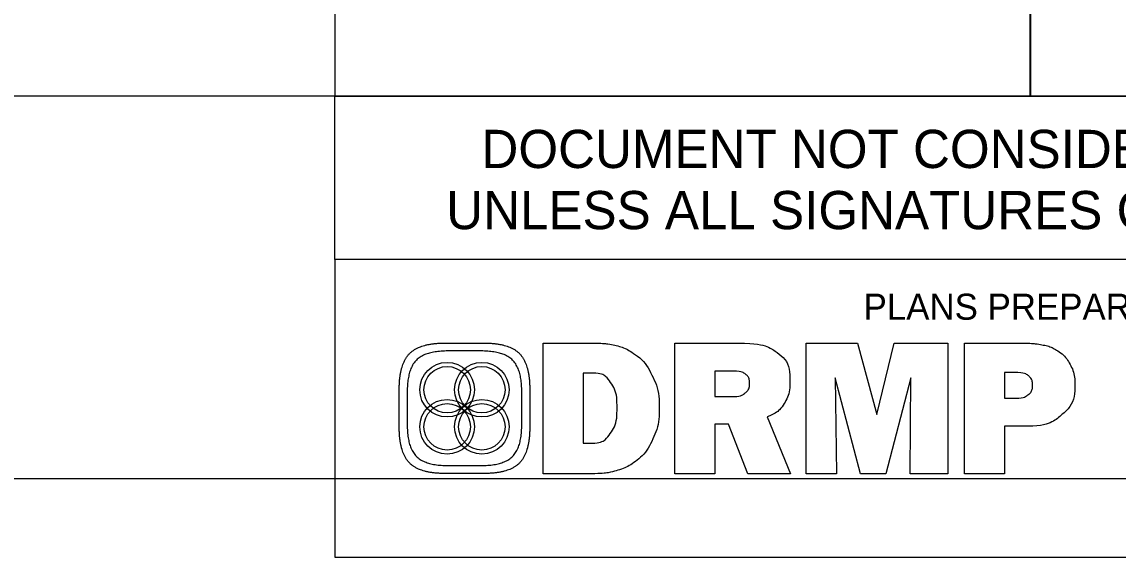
# Model space of a CAD drawing. Extents: x 573076.3 to 573113.7, y -55253.8 to -55199.3.
# Drawn here: x 573106.612 to 573109.767, y -55203.877 to -55202.337 of the extents above; entities that cross this region are included whole.
import ezdxf

# ---------------------------------------------------------------- set-up
doc = ezdxf.new("R2010")
doc.units = 0
for name, color, linetype in [('Pattern 1', 7, 'Continuous'), ('Pattern 2', 7, 'Continuous'), ('Pattern 3', 7, 'Continuous'), ('Scratch_Level_1', 7, 'Continuous'), ('Sheet Plan CELL', 7, 'Continuous'), ('Sheet Sticker Exception Certification CELL', 7, 'Continuous')]:
    doc.layers.add(name, color=color, linetype=linetype)

msp = doc.modelspace()

# ---------------------------------------------------------------- linework, layer by layer
at = {"layer": 'Pattern 1'}
for p, q in [((573107.8314, -55203.2607), (573107.9403, -55203.2607)), ((573108.8689, -55203.6369), (573108.8689, -55203.261)), ((573108.8689, -55203.261), (573109.0168, -55203.261)), ((573109.0168, -55203.261), (573109.073, -55203.4663)), ((573109.073, -55203.4663), (573109.1227, -55203.261)), ((573109.1227, -55203.261), (573109.2771, -55203.261)), ((573109.2771, -55203.261), (573109.2771, -55203.6369)), ((573107.9336, -55203.2836), (573107.8381, -55203.2836)), ((573109.026, -55203.6369), (573108.9528, -55203.3613)), ((573108.9528, -55203.3613), (573108.9568, -55203.6369)), ((573109.1705, -55203.3613), (573109.0989, -55203.6369)), ((573109.1687, -55203.6369), (573109.1705, -55203.3613)), ((573107.6981, -55203.5029), (573107.6981, -55203.394)), ((573108.0737, -55203.394), (573108.0737, -55203.5029)), ((573107.7211, -55203.4006), (573107.7211, -55203.4962)), ((573108.0507, -55203.4962), (573108.0507, -55203.4006)), ((573107.8381, -55203.6133), (573107.9336, -55203.6133)), ((573107.9403, -55203.6363), (573107.8314, -55203.6363)), ((573108.9568, -55203.6369), (573108.8689, -55203.6369)), ((573109.0989, -55203.6369), (573109.026, -55203.6369)), ((573109.2771, -55203.6369), (573109.1687, -55203.6369))]:
    msp.add_line(p, q, dxfattribs=at)
for points in [[(573108.252, -55203.6369), (573108.1124, -55203.6369), (573108.1124, -55203.261), (573108.257, -55203.261)], [(573108.7568, -55203.4727), (573108.8245, -55203.6369), (573108.701, -55203.6369), (573108.6452, -55203.4944), (573108.6059, -55203.4944), (573108.6059, -55203.6369), (573108.4915, -55203.6369), (573108.4915, -55203.261), (573108.6751, -55203.261)], [(573109.5069, -55203.4999), (573109.4402, -55203.4999), (573109.4402, -55203.6369), (573109.325, -55203.6369), (573109.325, -55203.261), (573109.4852, -55203.261)], [(573108.257, -55203.3474), (573108.2276, -55203.3474), (573108.2276, -55203.549), (573108.2536, -55203.549)], [(573108.659, -55203.3413), (573108.6059, -55203.3413), (573108.6059, -55203.4147), (573108.6606, -55203.4147)], [(573109.478, -55203.346), (573109.4402, -55203.346), (573109.4402, -55203.4197), (573109.4711, -55203.4197)]]:
    msp.add_lwpolyline(points, dxfattribs=at)
for points, degree in [([(573107.6981, -55203.394), (573107.6981, -55203.3206), (573107.7581, -55203.2607), (573107.8314, -55203.2607)], 2), ([(573107.9403, -55203.2607), (573108.0137, -55203.2607), (573108.0737, -55203.3206), (573108.0737, -55203.394)], 2), ([(573108.257, -55203.261), (573108.2798, -55203.261), (573108.3002, -55203.2631), (573108.3182, -55203.2671), (573108.3362, -55203.2712), (573108.3519, -55203.2774), (573108.3653, -55203.2859), (573108.391, -55203.3021), (573108.411, -55203.3245), (573108.4252, -55203.3529), (573108.4394, -55203.3814), (573108.4465, -55203.4134), (573108.4465, -55203.4488), (573108.4465, -55203.4802), (573108.4403, -55203.5096), (573108.4277, -55203.5369), (573108.4152, -55203.5642), (573108.3982, -55203.586), (573108.3766, -55203.6022), (573108.3606, -55203.614), (573108.3425, -55203.6228), (573108.3223, -55203.6284), (573108.3021, -55203.6341), (573108.2786, -55203.6369), (573108.252, -55203.6369)], 3), ([(573108.6751, -55203.261), (573108.7243, -55203.261), (573108.7612, -55203.2702), (573108.7857, -55203.2884), (573108.8102, -55203.3067), (573108.8224, -55203.3341), (573108.8224, -55203.3708), (573108.8224, -55203.3962), (573108.8168, -55203.4176), (573108.8056, -55203.4351), (573108.7944, -55203.4526), (573108.7782, -55203.4651), (573108.7568, -55203.4727)], 3), ([(573109.4852, -55203.261), (573109.5102, -55203.261), (573109.531, -55203.2626), (573109.5475, -55203.2657), (573109.564, -55203.2687), (573109.5777, -55203.2736), (573109.5886, -55203.2803), (573109.6063, -55203.2915), (573109.6196, -55203.3055), (573109.6287, -55203.3224), (573109.6378, -55203.3393), (573109.6423, -55203.3586), (573109.6423, -55203.3801), (573109.6423, -55203.4159), (573109.6299, -55203.4448), (573109.605, -55203.4669), (573109.5802, -55203.4889), (573109.5475, -55203.4999), (573109.5069, -55203.4999)], 3), ([(573107.8381, -55203.2836), (573107.7737, -55203.2836), (573107.7211, -55203.3363), (573107.7211, -55203.4006)], 2), ([(573108.0507, -55203.4006), (573108.0507, -55203.3363), (573107.998, -55203.2836), (573107.9336, -55203.2836)], 2), ([(573108.2536, -55203.549), (573108.2751, -55203.549), (573108.2924, -55203.5398), (573108.3054, -55203.5212), (573108.3184, -55203.5027), (573108.3249, -55203.478), (573108.3249, -55203.4472), (573108.3249, -55203.4166), (573108.3187, -55203.3924), (573108.3064, -55203.3744), (573108.2942, -55203.3564), (573108.2777, -55203.3474), (573108.257, -55203.3474)], 3), ([(573108.6606, -55203.4147), (573108.674, -55203.4147), (573108.6849, -55203.4113), (573108.6934, -55203.4044), (573108.7018, -55203.3975), (573108.7061, -55203.3887), (573108.7061, -55203.378), (573108.7061, -55203.3657), (573108.7021, -55203.3564), (573108.6943, -55203.3504), (573108.6864, -55203.3443), (573108.6747, -55203.3413), (573108.659, -55203.3413)], 3), ([(573109.4711, -55203.4197), (573109.4867, -55203.4197), (573109.4988, -55203.4165), (573109.5074, -55203.4099), (573109.5161, -55203.4034), (573109.5204, -55203.3943), (573109.5204, -55203.3827), (573109.5204, -55203.3709), (573109.5168, -55203.3618), (573109.5095, -55203.3555), (573109.5023, -55203.3491), (573109.4918, -55203.346), (573109.478, -55203.346)], 3), ([(573107.8314, -55203.6363), (573107.7581, -55203.6363), (573107.6981, -55203.5762), (573107.6981, -55203.5029)], 2), ([(573107.7211, -55203.4962), (573107.7211, -55203.5606), (573107.7737, -55203.6133), (573107.8381, -55203.6133)], 2), ([(573107.9336, -55203.6133), (573107.998, -55203.6133), (573108.0507, -55203.5606), (573108.0507, -55203.4962)], 2), ([(573108.0737, -55203.5029), (573108.0737, -55203.5762), (573108.0137, -55203.6363), (573107.9403, -55203.6363)], 2)]:
    msp.add_open_spline(points, degree=degree, dxfattribs=at)
at = {"layer": 'Pattern 2'}
for centre, radius in [((573107.8359, -55203.3951), 0.0785), ((573107.8359, -55203.3951), 0.0668), ((573107.9358, -55203.3951), 0.0785), ((573107.9358, -55203.3951), 0.0668), ((573107.8359, -55203.5018), 0.0785), ((573107.9358, -55203.5018), 0.0785), ((573107.8359, -55203.5018), 0.0668), ((573107.9358, -55203.5018), 0.0668)]:
    msp.add_circle(centre, radius, dxfattribs=at)
at = {"layer": 'Pattern 3'}
msp.add_lwpolyline([(573107.5132, -55203.8768), (573111.5139, -55203.8768), (573111.5139, -55203.0202), (573107.5132, -55203.0202)], close=True, dxfattribs=at)
at = {"layer": 'Scratch_Level_1'}
for p, q in [((573111.5139, -55202.5502), (573076.2547, -55202.5502)), ((573082.5142, -55203.6502), (573112.708, -55203.6502))]:
    msp.add_line(p, q, dxfattribs=at)
at = {"layer": 'Sheet Plan CELL'}
msp.add_line((573109.5142, -55200.3002), (573109.5144, -55202.5494), dxfattribs=at)
for points in [[(573109.5142, -55200.3002), (573107.5132, -55200.3002), (573107.5132, -55202.5502), (573109.5142, -55202.5502)], [(573109.5142, -55200.3002), (573111.5142, -55200.3002), (573111.5142, -55202.5502), (573109.5142, -55202.5502)]]:
    msp.add_lwpolyline(points, close=True, dxfattribs=at)
at = {"layer": 'Sheet Sticker Exception Certification CELL'}
for p, q in [((573107.5132, -55203.0202), (573107.5132, -55202.5502)), ((573107.5132, -55202.5502), (573111.5139, -55202.5502)), ((573111.5139, -55203.0202), (573107.5132, -55203.0202))]:
    msp.add_line(p, q, dxfattribs=at)

# ---------------------------------------------------------------- texts
at = {"layer": 'Pattern 2'}
msp.add_text('PLANS PREPARED BY:', height=0.074995, rotation=360, dxfattribs=at).set_placement((573109.0345, -55203.1937))
at = {"layer": 'Sheet Sticker Exception Certification CELL'}
for s, p in [('DOCUMENT NOT CONSIDERED FINAL', (573107.9346, -55202.7571)), ('UNLESS ALL SIGNATURES COMPLETED', (573107.8332, -55202.9331))]:
    msp.add_text(s, height=0.11, dxfattribs=at).set_placement(p)

doc.saveas('drawing.dxf')
